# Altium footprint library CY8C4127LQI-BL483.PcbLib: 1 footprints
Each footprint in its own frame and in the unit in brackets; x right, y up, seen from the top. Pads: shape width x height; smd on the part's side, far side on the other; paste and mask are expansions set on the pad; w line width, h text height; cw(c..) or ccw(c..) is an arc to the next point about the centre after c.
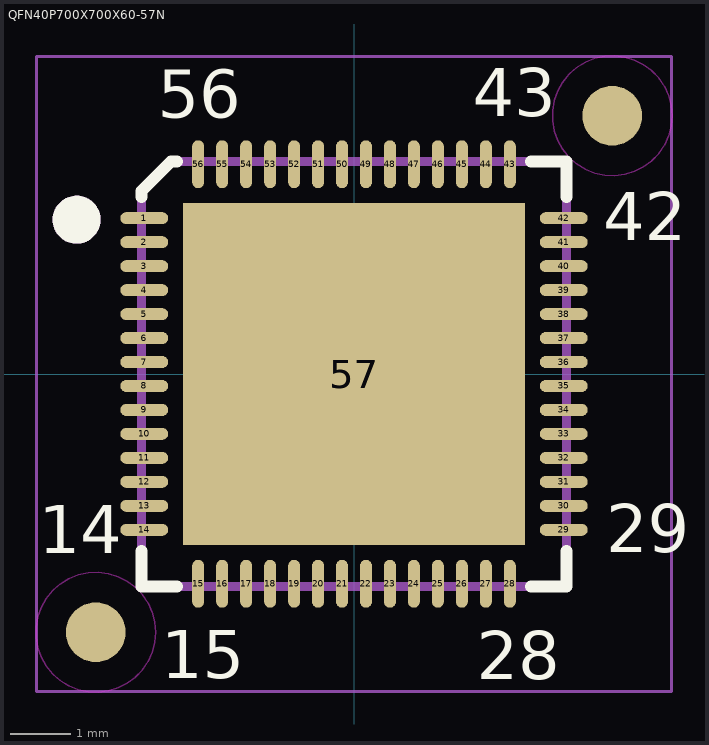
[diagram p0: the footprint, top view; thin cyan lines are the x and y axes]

## QFN40P700X700X60-57N [mm]
height 0.6
pads (59):
  oval 0.8x0.2 smd mask+0: 1(-3.5,2.6) 2(-3.5,2.2) 3(-3.5,1.8) 4(-3.5,1.4) 5(-3.5,1) 6(-3.5,0.6) 7(-3.5,0.2) 8(-3.5,-0.2) 9(-3.5,-0.6) 10(-3.5,-1) 11(-3.5,-1.4) 12(-3.5,-1.8) 13(-3.5,-2.2) 14(-3.5,-2.6) 29(3.5,-2.6) 30(3.5,-2.2) 31(3.5,-1.8) 32(3.5,-1.4) 33(3.5,-1) 34(3.5,-0.6) 35(3.5,-0.2) 36(3.5,0.2) 37(3.5,0.6) 38(3.5,1) 39(3.5,1.4) 40(3.5,1.8) 41(3.5,2.2) 42(3.5,2.6)
  oval 0.2x0.8 smd mask+0: 15(-2.6,-3.5) 16(-2.2,-3.5) 17(-1.8,-3.5) 18(-1.4,-3.5) 19(-1,-3.5) 20(-0.6,-3.5) 21(-0.2,-3.5) 22(0.2,-3.5) 23(0.6,-3.5) 24(1,-3.5) 25(1.4,-3.5) 26(1.8,-3.5) 27(2.2,-3.5) 28(2.6,-3.5) 43(2.6,3.5) 44(2.2,3.5) 45(1.8,3.5) 46(1.4,3.5) 47(1,3.5) 48(0.6,3.5) 49(0.2,3.5) 50(-0.2,3.5) 51(-0.6,3.5) 52(-1,3.5) 53(-1.4,3.5) 54(-1.8,3.5) 55(-2.2,3.5) 56(-2.6,3.5)
  rect 5.7x5.7 smd paste-5.7 mask+0: 57(0,0)
  round 1 smd mask+0.5: ""(-4.31,-4.31) ""(4.31,4.31)
Top Layer keep-out:
  circle w0.025: c-4.31,-4.31 r1
  circle w0.025: c4.31,4.31 r1
Top Overlay:
  circle w0.4: c-4.629,2.575 r0.2
  lines w0.2: -3.55,-2.95 -3.55,-3.55 -2.95,-3.55 ; -3.55,2.95 -3.55,3.05 -3.05,3.55 -2.95,3.55 ; 2.951,-3.55 3.55,-3.55 3.55,-2.95 ; 2.95,3.55 3.55,3.55 3.55,2.951
  text "56" at -3.278,4.279 h0.8
  text "43" at 1.984,4.298 h0.8
  text "42" at 4.159,2.234 h0.8
  text "29" at 4.206,-2.972 h0.8
  text "28" at 2.049,-5.092 h0.8
  text "15" at -3.213,-5.073 h0.8
  text ".Designator" at -2.667,5.588 h0.8
  text "14" at -5.258,-2.991 h0.8
Top Paste:
  region: -0.25,-2.35 -2.35,-2.35 -2.35,-0.25 -0.25,-0.25
  region: 2.35,-2.35 0.25,-2.35 0.25,-0.25 2.35,-0.25
  region: 2.35,0.25 0.25,0.25 0.25,2.35 2.35,2.35
  region: -0.25,0.25 -2.35,0.25 -2.35,2.35 -0.25,2.35
Mechanical 13:
  circle w0.4: c-4.629,2.575 r0.2
  lines w0.15: -3.55,-3.55 3.55,-3.55 3.55,3.55 -3.05,3.55 -3.55,3.05 -3.55,-3.55
  text ".Designator" at -2.921,-0.254 h0.8
Mechanical 14:
  text "C100M200K200" at -4.05,-10.144 h0.8
  text "S570P4S210" at -3.308,-8.805 h0.8
  text "B80_20" at -1.975,-7.601 h0.8
  text "QFN40P700X700X60-57N" at -6.35,7.366 h0.8
Mechanical 15:
  lines w0.05: -5.295,-5.295 -5.295,5.295 5.295,5.295 5.295,-5.295 -5.295,-5.295
3D body: height 0.6, standoff 0, extent -3.551,-3.551 3.551,3.551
